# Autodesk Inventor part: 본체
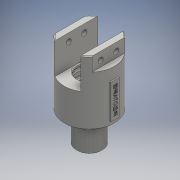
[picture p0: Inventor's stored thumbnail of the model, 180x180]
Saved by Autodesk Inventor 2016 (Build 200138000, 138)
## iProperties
Created: 2019-02
Part Number: 본체
Material: 일반
Document SubType Name: Modeling
Designer: 605-11
Density: 1 g/cm^3
Appearance: 기본값
Author: 605-11
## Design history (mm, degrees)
sketch "스케치1"
  geometry: C1 r 29 at (0, 0); 1 further point
  constraints: 1 centre point, 1 coincident
  dimensions: "d0" = 58 diameter of C1
extrude "돌출1" new body sketch "스케치1" distance "d1" = 74; taper "d2" = 0 deg
sketch "스케치2"
  geometry: L1 (15, 0)-(-15, 0); L2 (-15, 0)-(-15, -36); L3 (-15, -36)-(15, -36); L4 (15, -36)-(15, 0); 2 further points
  constraints: 8 end point, 2 parallel, 1 coincident, 1 horizontal, 1 midpoint, 1 perpendicular
  dimensions: "d3" = 30 distance of L1.start L1.end; "d4" = 36 distance of L3.end L1.start
extrude "돌출2" cut sketch "스케치2" stored distance "d5" = 60; taper "d6" = 0 deg
sketch "스케치3"
  geometry: L1 (29, 0)-(22, 0); L2 (22, 0)-(22, -16); L3 (22, -16)-(29, -16); L4 (29, -16)-(29, 0); L5 (29, 0)-(29, -74) reference; L6 (15, 0)-(29, 0) reference; L7 (0, 0)-(0, -110.239); L8 (-29, -16)-(-29, 0); L9 (-22, -16)-(-29, -16); L10 (-22, 0)-(-22, -16); L11 (-29, 0)-(-22, 0)
  constraints: 18 end point, 4 symmetric about line, 2 collinear, 2 parallel, 1 horizontal, 1 perpendicular, 1 vertical
  dimensions: "d7" = 16 distance of L3.end L1.start; "d9" = 22 distance from line of L7.start L2
extrude "돌출3" cut sketch "스케치3" stored distance "d10" = 60; taper "d11" = 0 deg
sketch "스케치4"
  geometry: L1 (0, 0)-(0, -116.384); C1 r 3 at (9, -9); C2 r 3 at (-9, -9)
  constraints: 2 centre point, 2 end point, 1 symmetric about line, 1 vertical, 1 other
  dimensions: "d12" = 9 horizontal distance of C1.centre L1.start; "d13" = 9 horizontal distance of L1.start C1.centre; "d14" = 6 diameter of C1
extrude "돌출4" cut sketch "스케치4" stored distance "d15" = 60; taper "d16" = 0 deg
node "작업 평면1"
sketch "스케치5"
  geometry: L1 (5, -29)-(-5, -29); L2 (-5, -29)-(-5, -69); L3 (-5, -69)-(5, -69); L4 (5, -69)-(5, -29); L5 (-29, -74)-(29, -74) reference; 1 further point
  constraints: 8 end point, 2 parallel, 1 horizontal, 1 perpendicular
  dimensions: "d18" = 40 distance of L3.end L1.start; "d19" = 5 distance between parallel lines of L3 L5; "d21" = 5 distance from line of point (0, 0) L2; "d22" = 10 distance between parallel lines of L2 L4
extrude "돌출5" join sketch "스케치5" stored distance "d23" = 2; taper "d24" = 0 deg
sketch "스케치6"
  geometry: L1 (29, 5)-(29, -5) reference; 3 further points
  constraints: 1 coincident, 1 horizontal alignment, 1 other
  dimensions: "d25" = 20 distance from line of L1 point (49, 0)
feature "엠보싱1" sketch "스케치6" dims "d26" = 0.5, "d27" = 0
sketch "스케치7"
  geometry: C1 r 13 at (0, 0); 1 further point
  constraints: 1 centre point, 1 coincident
  dimensions: "d28" = 26 diameter of C1
extrude "돌출6" join sketch "스케치7" distance "d29" = 5; taper "d30" = 0 deg
sketch "스케치8"
  geometry: C1 r 15 at (0, 0); 1 further point
  constraints: 1 centre point, 1 coincident
  dimensions: "d31" = 30 diameter of C1
extrude "돌출7" join sketch "스케치8" distance "d32" = 29; taper "d33" = 0 deg
sketch "스케치9"
  geometry: L1 (0, 0)-(0, -226.433); L2 (14, -36)-(14, -38.65); L3 (14, -38.65)-(16.2, -38.65); L4 (17, -39.45)-(17, -42.55); L5 (16.2, -43.35)-(14, -43.35); L6 (14, -43.35)-(14, -47.65); L7 (14, -47.65)-(16.2, -47.65); L8 (17, -48.45)-(17, -51.55); L9 (16.2, -52.35)-(14, -52.35); L10 (14, -52.35)-(14, -56); L11 (14, -56)-(16, -56); L12 (16, -56)-(16, -63); L13 (16, -63)-(0, -63); L14 (-15, -36)-(15, -36) reference; L15 (17, -41)-(-8.438, -41); L16 (17, -50)-(-8.438, -50); L17 (0, -63)-(0, -36); L18 (14, -36)-(0, -36); A1 r 0.8 centre (16.2, -39.45) between (17, -39.45) and (16.2, -38.65); A2 r 0.8 centre (16.2, -42.55) between (16.2, -43.35) and (17, -42.55); A3 r 0.8 centre (16.2, -48.45) between (17, -48.45) and (16.2, -47.65); A4 r 0.8 centre (16.2, -51.55) between (16.2, -52.35) and (17, -51.55); 2 further points
  constraints: 34 end point, 10 perpendicular, 8 point on circle, 8 tangent, 6 point on line, 4 centre point, 4 collinear, 3 equal radius, 3 midpoint, 2 horizontal, 2 vertical
  dimensions: "d34" = 28 diameter of L2 L1; "d35" = 34 diameter of L4 L1; "d36" = 4.7 distance between parallel lines of L5 L3; "d38" = 4.7 distance of point (17, -47.65) point (17, -52.35); "d39" = 9 distance between parallel lines of L16 L15; "d41" = 32 diameter of L12 L1; "d42" = 7 distance of L11.end L12.end; "d43" = 27 distance between parallel lines of L14 L13; "d44" = 5 vertical distance of L14.end L15.start; "d45" = 0.8 radius of A1
revolve "회전1" sketch "스케치9" stored, may be unused: angle "d46" = 90 deg
sketch "스케치10"
  geometry: 2 further points
  constraints: 1 coincident
hole "구멍1" sketch "스케치10" at (0, 0) diameter "d47" = 12.376; stored, may be unused: countersink angle "d51" = 90 deg, drill point angle "d53" = 118 deg; dims "d48" = 18, "d49" = 4, "d50" = 2, "d52" = 22
chamfer "모따기1" distance "d54" = 1; stored, may be unused: second distance "d55" = 2, angle "d56" = 45 deg
feature "스레드1" dims "d57" = 10, "d58" = 0
sketch "스케치11"
  geometry: C1 r 4 at (0, 0); 1 further point
  constraints: 1 centre point, 1 coincident
  dimensions: "d59" = 8 diameter of C1
extrude "돌출8" cut sketch "스케치11" distance "d60" = 39; taper "d61" = 0 deg
node "솔리드1"
other parameters: "d17" = 29
